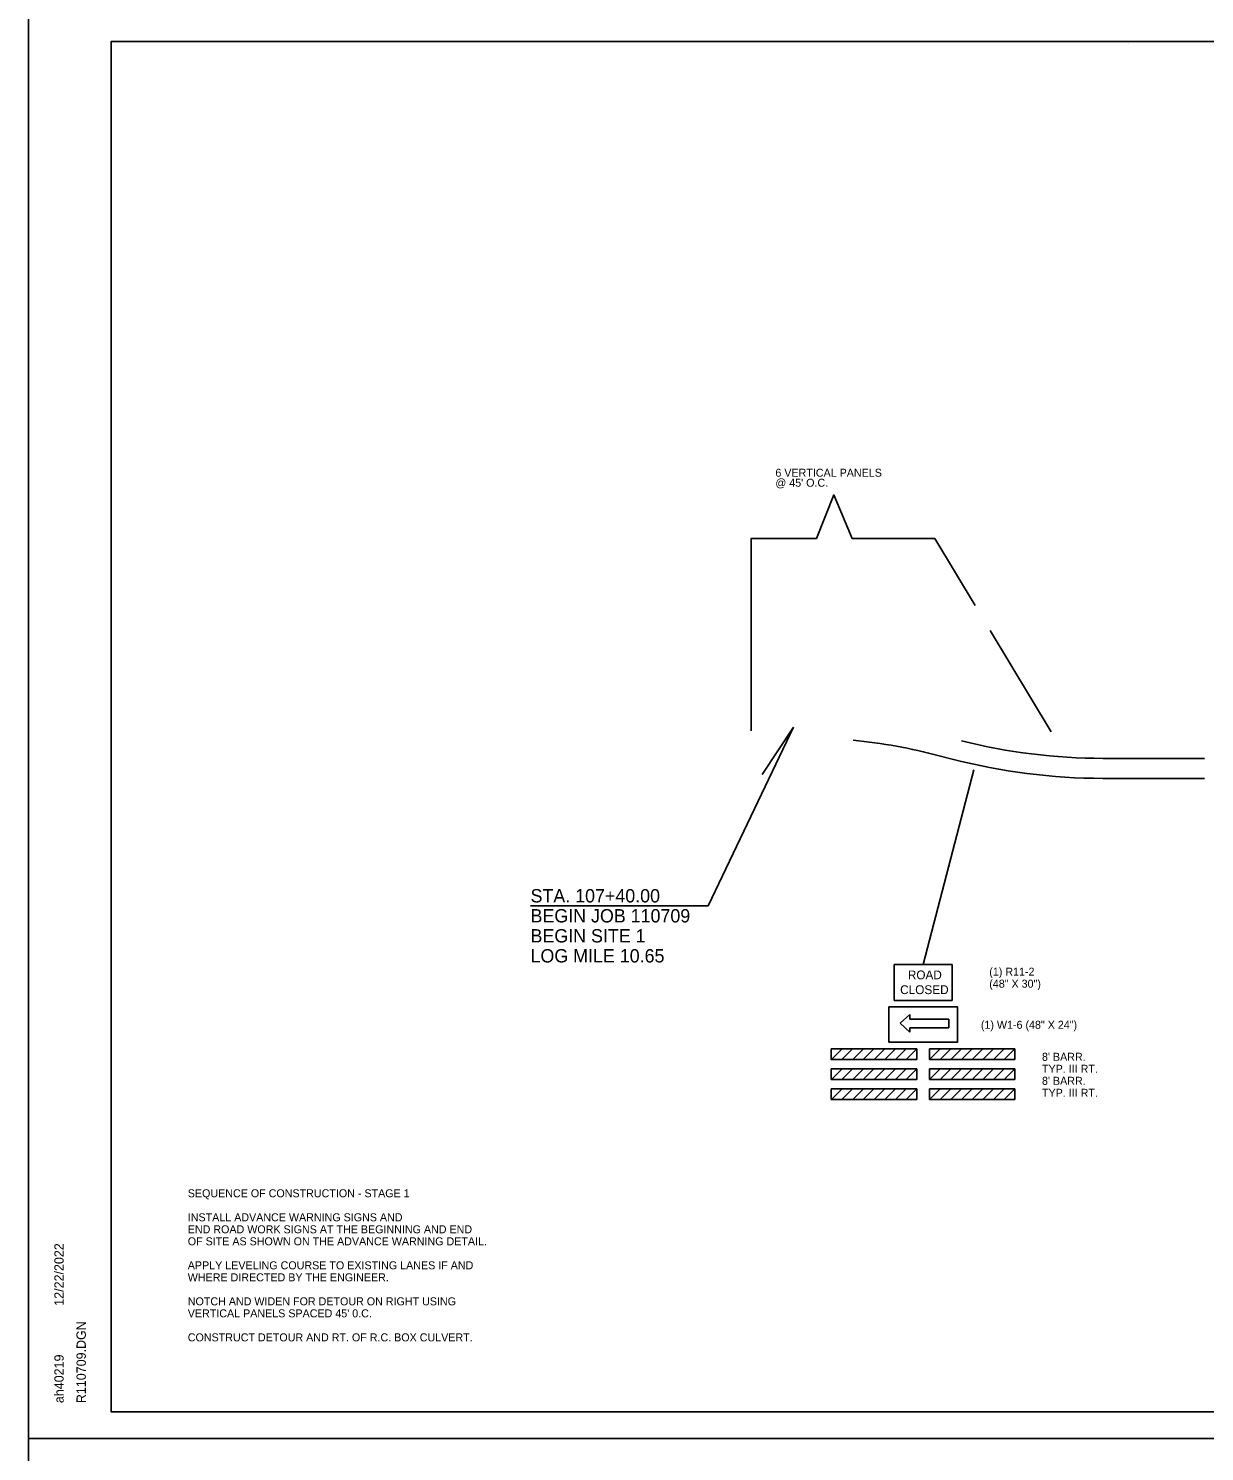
# Model space of a CAD drawing. Extents: x 2829243 to 2838161, y 467639 to 474695.
# Drawn here: x 2829486 to 2830368, y 471502 to 472569 of the extents above; entities that cross this region are included whole.
import ezdxf

# ---------------------------------------------------------------- set-up
doc = ezdxf.new("R2010")
doc.units = 0
for name, color, linetype in [('R_Border', 7, 'Continuous'), ('R_Border Notes', 7, 'Continuous'), ('R_Dimension', 7, 'Continuous'), ('R_MOT', 7, 'Continuous'), ('R_No Plot', 7, 'Continuous')]:
    doc.layers.add(name, color=color, linetype=linetype)

msp = doc.modelspace()

# ---------------------------------------------------------------- linework, layer by layer
at = {"layer": 'R_Border'}
for p, q in [((2829548.2, 472559), (2831129.1, 472559)), ((2829548.2, 471531.7), (2829548.2, 472559)), ((2830310.8, 472557.7), (2830310.8, 472557.7)), ((2830310.8, 472557.7), (2830310.8, 472557.7)), ((2829548.2, 471531.7), (2829548.2, 471531.7)), ((2831129.1, 471531.7), (2829548.2, 471531.7))]:
    msp.add_line(p, q, dxfattribs=at)
at = {"layer": 'R_Dimension'}
for p, q in [((2829995.6, 471911.1), (2830059.6, 472045.1)), ((2830036, 472009.5), (2830059.6, 472045.1)), ((2829995.6, 471911.1), (2829862.5, 471911.1))]:
    msp.add_line(p, q, dxfattribs=at)
at = {"layer": 'R_MOT'}
for p, q in [((2830194.8, 472012.9), (2830156.8, 471867.2)), ((2830135.1, 471840), (2830135.1, 471867.2)), ((2830135.1, 471867.2), (2830178.6, 471867.2)), ((2830178.6, 471840), (2830178.6, 471867.2)), ((2830135.1, 471840), (2830178.6, 471840)), ((2830139.5, 471823), (2830146.7, 471829.5)), ((2830146.7, 471826.2), (2830146.7, 471829.5)), ((2830146.7, 471816.4), (2830139.5, 471823)), ((2830176.1, 471826.2), (2830146.7, 471826.2)), ((2830176.1, 471819.7), (2830146.7, 471819.7)), ((2830146.7, 471819.7), (2830146.7, 471816.4)), ((2830176.1, 471819.7), (2830176.1, 471826.2)), ((2830087.8, 471803.8), (2830151.9, 471803.8)), ((2830087.8, 471795.8), (2830087.8, 471803.8)), ((2830151.9, 471795.8), (2830151.9, 471803.8)), ((2830161.4, 471803.8), (2830225.4, 471803.8)), ((2830161.4, 471795.8), (2830161.4, 471803.8)), ((2830225.4, 471795.8), (2830225.4, 471803.8)), ((2830087.8, 471795.8), (2830151.9, 471795.8)), ((2830087.8, 471788.9), (2830151.9, 471788.9)), ((2830087.8, 471780.9), (2830087.8, 471788.9)), ((2830151.8, 471795.8), (2830151.9, 471795.8)), ((2830151.9, 471780.9), (2830151.9, 471788.9)), ((2830151.9, 471780.9), (2830151.9, 471788.9)), ((2830161.4, 471795.8), (2830225.4, 471795.8)), ((2830161.4, 471788.9), (2830225.4, 471788.9)), ((2830161.4, 471780.9), (2830161.4, 471788.9)), ((2830225.4, 471795.8), (2830225.4, 471795.8)), ((2830225.4, 471780.9), (2830225.4, 471788.9)), ((2830225.4, 471780.9), (2830225.4, 471788.9)), ((2830087.8, 471780.9), (2830151.9, 471780.9)), ((2830161.4, 471780.9), (2830225.4, 471780.9)), ((2830087.8, 471774), (2830151.9, 471774)), ((2830087.8, 471766), (2830087.8, 471774)), ((2830087.8, 471766), (2830151.9, 471766)), ((2830151.9, 471766), (2830151.9, 471774)), ((2830161.4, 471774), (2830225.4, 471774)), ((2830161.4, 471766), (2830161.4, 471774)), ((2830161.4, 471766), (2830225.4, 471766)), ((2830225.4, 471766), (2830225.4, 471774))]:
    msp.add_line(p, q, dxfattribs=at)
for points in [[(2830195.8, 472136.1), (2830165.4, 472186.4), (2830103.6, 472186.4), (2830089.7, 472219.1), (2830076.7, 472186.4), (2830027.8, 472186.4), (2830027.8, 472042.2)], [(2830252.7, 472041.6), (2830207, 472117.4)]]:
    msp.add_lwpolyline(points, dxfattribs=at)
for points in [[(2830131.1, 471808.9), (2830182.6, 471808.9), (2830182.6, 471835.3), (2830131.1, 471835.3)], [(2830103.9, 471803.8), (2830096, 471803.8), (2830088, 471795.8), (2830095.9, 471795.8)], [(2830119.9, 471803.8), (2830112, 471803.8), (2830104, 471795.8), (2830111.9, 471795.8)], [(2830135.9, 471803.8), (2830128, 471803.8), (2830120, 471795.8), (2830127.9, 471795.8)], [(2830151.9, 471803.8), (2830144, 471803.8), (2830136, 471795.8), (2830143.9, 471795.8)], [(2830177.4, 471803.8), (2830169.5, 471803.8), (2830161.5, 471795.8), (2830169.4, 471795.8)], [(2830193.4, 471803.8), (2830185.5, 471803.8), (2830177.5, 471795.8), (2830185.4, 471795.8)], [(2830209.4, 471803.8), (2830201.5, 471803.8), (2830193.5, 471795.8), (2830201.4, 471795.8)], [(2830225.4, 471803.8), (2830217.5, 471803.8), (2830209.5, 471795.8), (2830217.4, 471795.8)], [(2830103.9, 471788.9), (2830096, 471788.9), (2830088, 471780.9), (2830095.9, 471780.9)], [(2830119.9, 471788.9), (2830112, 471788.9), (2830104, 471780.9), (2830111.9, 471780.9)], [(2830135.9, 471788.9), (2830128, 471788.9), (2830120, 471780.9), (2830127.9, 471780.9)], [(2830151.9, 471788.9), (2830144, 471788.9), (2830136, 471780.9), (2830143.9, 471780.9)], [(2830177.4, 471788.9), (2830169.5, 471788.9), (2830161.5, 471780.9), (2830169.4, 471780.9)], [(2830193.4, 471788.9), (2830185.5, 471788.9), (2830177.5, 471780.9), (2830185.4, 471780.9)], [(2830209.4, 471788.9), (2830201.5, 471788.9), (2830193.5, 471780.9), (2830201.4, 471780.9)], [(2830225.4, 471788.9), (2830217.5, 471788.9), (2830209.5, 471780.9), (2830217.4, 471780.9)], [(2830103.9, 471774), (2830096, 471774), (2830088, 471766), (2830095.9, 471766)], [(2830119.9, 471774), (2830112, 471774), (2830104, 471766), (2830111.9, 471766)], [(2830135.9, 471774), (2830128, 471774), (2830120, 471766), (2830127.9, 471766)], [(2830151.9, 471774), (2830144, 471774), (2830136, 471766), (2830143.9, 471766)], [(2830177.4, 471774), (2830169.5, 471774), (2830161.5, 471766), (2830169.4, 471766)], [(2830193.4, 471774), (2830185.5, 471774), (2830177.5, 471766), (2830185.4, 471766)], [(2830209.4, 471774), (2830201.5, 471774), (2830193.5, 471766), (2830201.4, 471766)], [(2830225.4, 471774), (2830217.5, 471774), (2830209.5, 471766), (2830217.4, 471766)]]:
    msp.add_lwpolyline(points, close=True, dxfattribs=at)
at = {"layer": 'R_No Plot'}
for p, q in [((2830168.8, 472023.6), (2830178.5, 472021.1)), ((2830291.5, 472021.6), (2830367.6, 472021.6)), ((2830291.5, 472006.6), (2830367.6, 472006.6)), ((2829486.2, 471511.8), (2831152.9, 471511.8)), ((2829486.2, 471511.8), (2831152.9, 471511.8))]:
    msp.add_line(p, q, dxfattribs=at)
for points in [[(2829486.2, 472578.4), (2831152.9, 472578.4), (2831152.9, 471511.8), (2829486.2, 471511.8)], [(2830717.8, 472559), (2830815.9, 472559), (2830815.9, 472509.6), (2830896.5, 472509.6), (2831012.5, 472509.6), (2831012.5, 472387.9), (2831129.1, 472387.9), (2831129.1, 471531.7), (2829548.2, 471531.7), (2829548.2, 472559)], [(2829486.2, 471511.8), (2831152.9, 471511.8), (2831152.9, 470445.1), (2829486.2, 470445.1)]]:
    msp.add_lwpolyline(points, close=True, dxfattribs=at)
for centre, radius, start, end in [((2830059.6, 471604.4), 433.2, 75.3961, 84.0769), ((2830291.5, 472454.8), 433.2, 255.829, 270), ((2830291.5, 472454.8), 448.2, 255.3961, 270)]:
    msp.add_arc(centre, radius, start, end, dxfattribs=at)

# ---------------------------------------------------------------- texts
at = {"layer": 'R_Border'}
for s, p in [('12/22/2022', (2829512.6, 471611.3)), ('R110709.DGN', (2829529.2, 471538.3)), ('ah40219', (2829512.6, 471538.3))]:
    msp.add_text(s, height=7, rotation=90, dxfattribs=at).set_placement(p)
at = {"layer": 'R_Border Notes'}
for s, p in [('SEQUENCE OF CONSTRUCTION - STAGE 1', (2829605.6, 471692.6)), ('INSTALL ADVANCE WARNING SIGNS AND ', (2829605.6, 471674.6)), ('END ROAD WORK SIGNS AT THE BEGINNING AND END', (2829605.6, 471665.6)), ('OF SITE AS SHOWN ON THE ADVANCE WARNING DETAIL.', (2829605.6, 471656.6)), ('APPLY LEVELING COURSE TO EXISTING LANES IF AND', (2829605.6, 471638.6)), ('WHERE DIRECTED BY THE ENGINEER.', (2829605.6, 471629.6)), ('NOTCH AND WIDEN FOR DETOUR ON RIGHT USING', (2829605.6, 471611.6)), ("VERTICAL PANELS SPACED 45' 0.C.", (2829605.6, 471602.6)), ('CONSTRUCT DETOUR AND RT. OF R.C. BOX CULVERT.', (2829605.6, 471584.6))]:
    msp.add_text(s, height=6, dxfattribs=at).set_placement(p)
at = {"layer": 'R_Dimension'}
for s, p in [('STA. 107+40.00', (2829862.5, 471913.6)), ('BEGIN JOB 110709', (2829862.5, 471898.6)), ('BEGIN SITE 1', (2829862.5, 471883.6)), ('LOG MILE 10.65', (2829862.5, 471868.6))]:
    msp.add_text(s, height=10, rotation=0.0006, dxfattribs=at).set_placement(p)
at = {"layer": 'R_MOT'}
for s, p in [('6 VERTICAL PANELS', (2830046, 472232.7)), ("@ 45' O.C.", (2830046, 472225.2))]:
    msp.add_text(s, height=6, rotation=0.0055, dxfattribs=at).set_placement(p)
for s, height, p in [('ROAD', 6.58, (2830145.3, 471856)), ('(1) R11-2', 6, (2830206.3, 471858.7)), ('CLOSED', 6.61, (2830139.5, 471844.9)), ('(48" X 30")', 6, (2830206.3, 471849.7)), ('(1) W1-6 (48" X 24")', 6, (2830200, 471818.9)), ("8' BARR.", 6, (2830245.8, 471794.9)), ('TYP. III RT.', 6, (2830245.8, 471785.9)), ("8' BARR.", 6, (2830245.8, 471776.9)), ('TYP. III RT.', 6, (2830245.8, 471767.9))]:
    msp.add_text(s, height=height, dxfattribs=at).set_placement(p)

doc.saveas('drawing.dxf')
